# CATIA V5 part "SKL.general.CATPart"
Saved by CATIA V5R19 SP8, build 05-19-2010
Part number: SKL.general
Bounding box of the stored display mesh (mm): x -12 to 0, y -25 to 25, z -25 to 25
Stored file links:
  G:\EU_thinkMotion\CFAO_2010\MMS_groupe3\MMS_groupe3\jbonnamy\jbonnamy_cfao\SKL.general.CATPart
  G:\EU_thinkMotion\CFAO_2010\MMS_groupe3\MMS_groupe3\jbonnamy\jbonnamy_cfao\jbonnamy_suspension.arriere.directionnelle.CATProduct
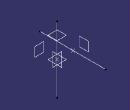
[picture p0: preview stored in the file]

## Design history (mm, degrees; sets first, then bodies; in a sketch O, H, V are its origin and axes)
External parameters (linked from other documents)
  External.Distance.support.10.centre.pignon = 16 mm
  External.Distance.centre.pivot.moyeu = 20.5 mm
  `External.Distance.centre.pivot.plan moteur` = 13.5 mm
  External.Diametre.primitif.roue = 18 mm
  External.Diametre.primitif.vis.sans.fin = 6 mm
Body1 (main body)
  Point1 "Centre.pignon": (0, 0, 0)
  Line1 "Axe.pivot": type Normal, RefPoint Point1, RefSkin xy-plane, Start -25, End 25
  Point2 "Point.vis.sans.fin": (-12 {= -(External.Diametre.primitif.roue +External.Diametre.primitif.vis.sans.fin )/2}, 0, 0)
  Line2 "Axe.vis.sans.fin": type Normal, RefPoint Point2, RefSkin zx-plane, Start -25, End 25
  Plane1 "Plan.haut.support.10": type Offset, RefPlane xy-plane, Offset 16 {= External.Distance.support.10.centre.pignon}
  Plane2 "Plan.moyeu": type Offset, RefPlane yz-plane, Offset 20.5 {= External.Distance.centre.pivot.moyeu}, reversed
  Plane3 "Plan.moteur": type Offset, RefPlane zx-plane, Offset 13.5 {= `External.Distance.centre.pivot.plan moteur`}, reversed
